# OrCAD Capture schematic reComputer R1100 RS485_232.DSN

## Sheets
1 01 RS485: size A3; rev: v1.0
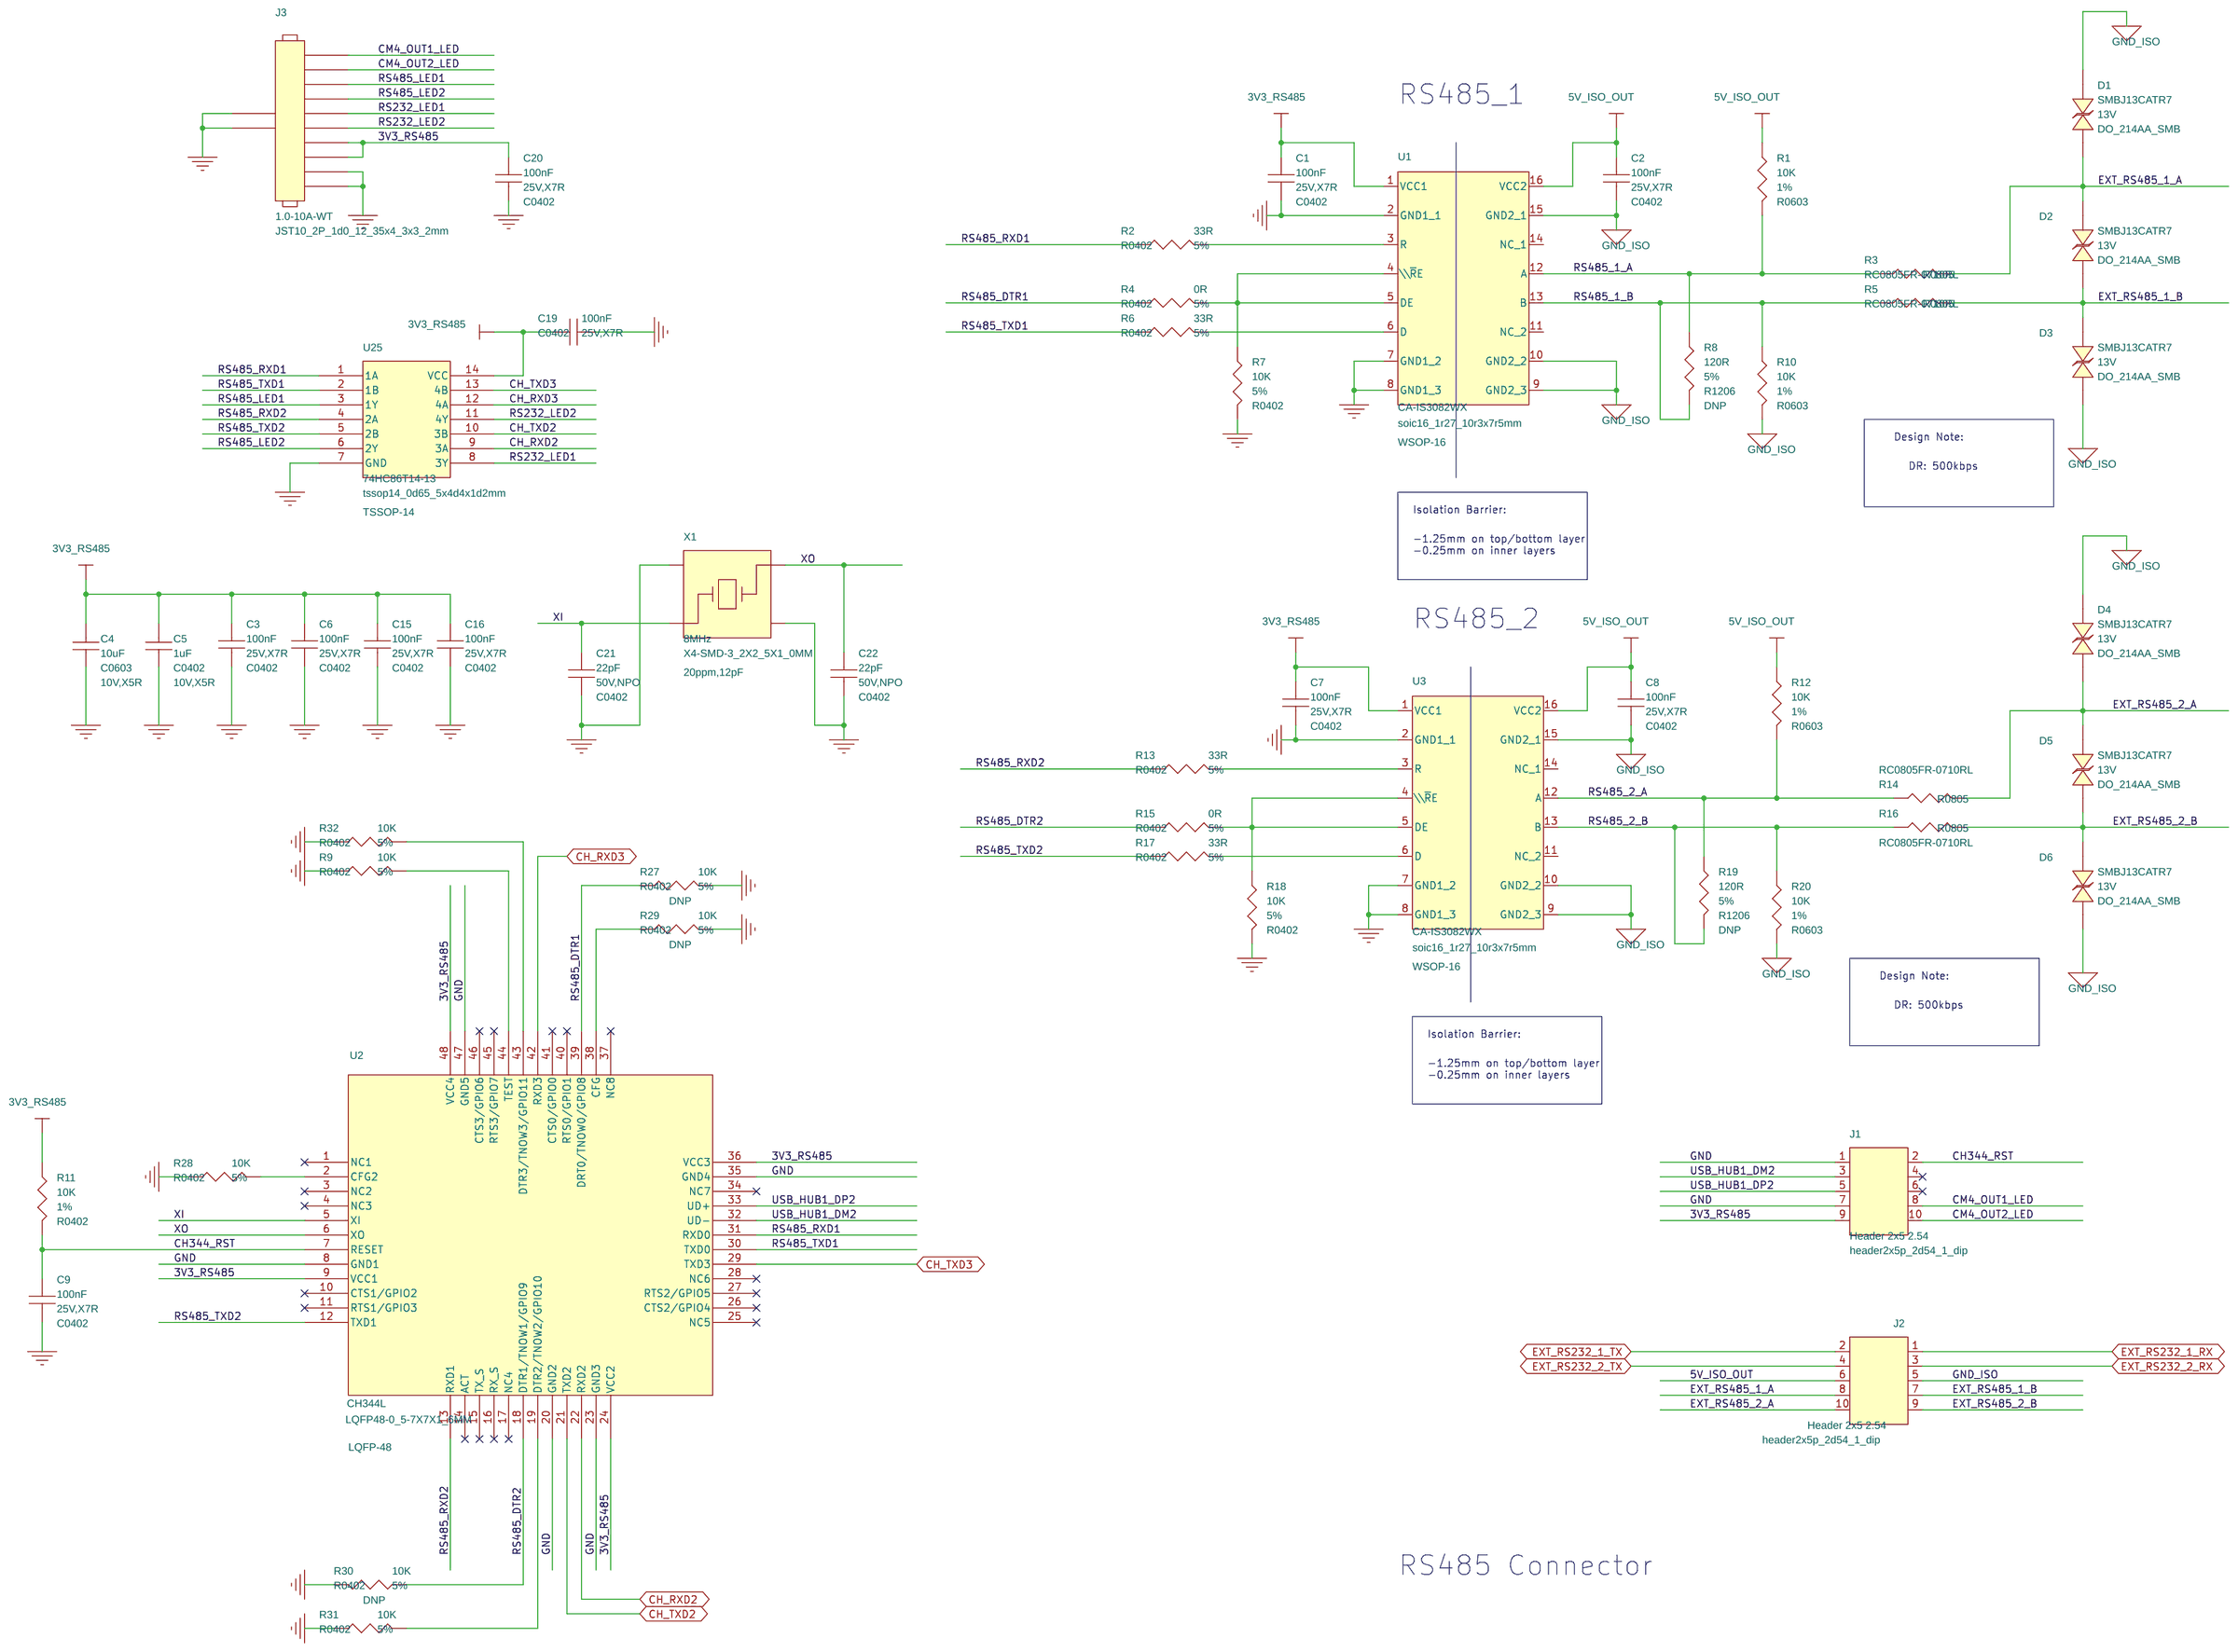
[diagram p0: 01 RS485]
2 02 RS232: size A3
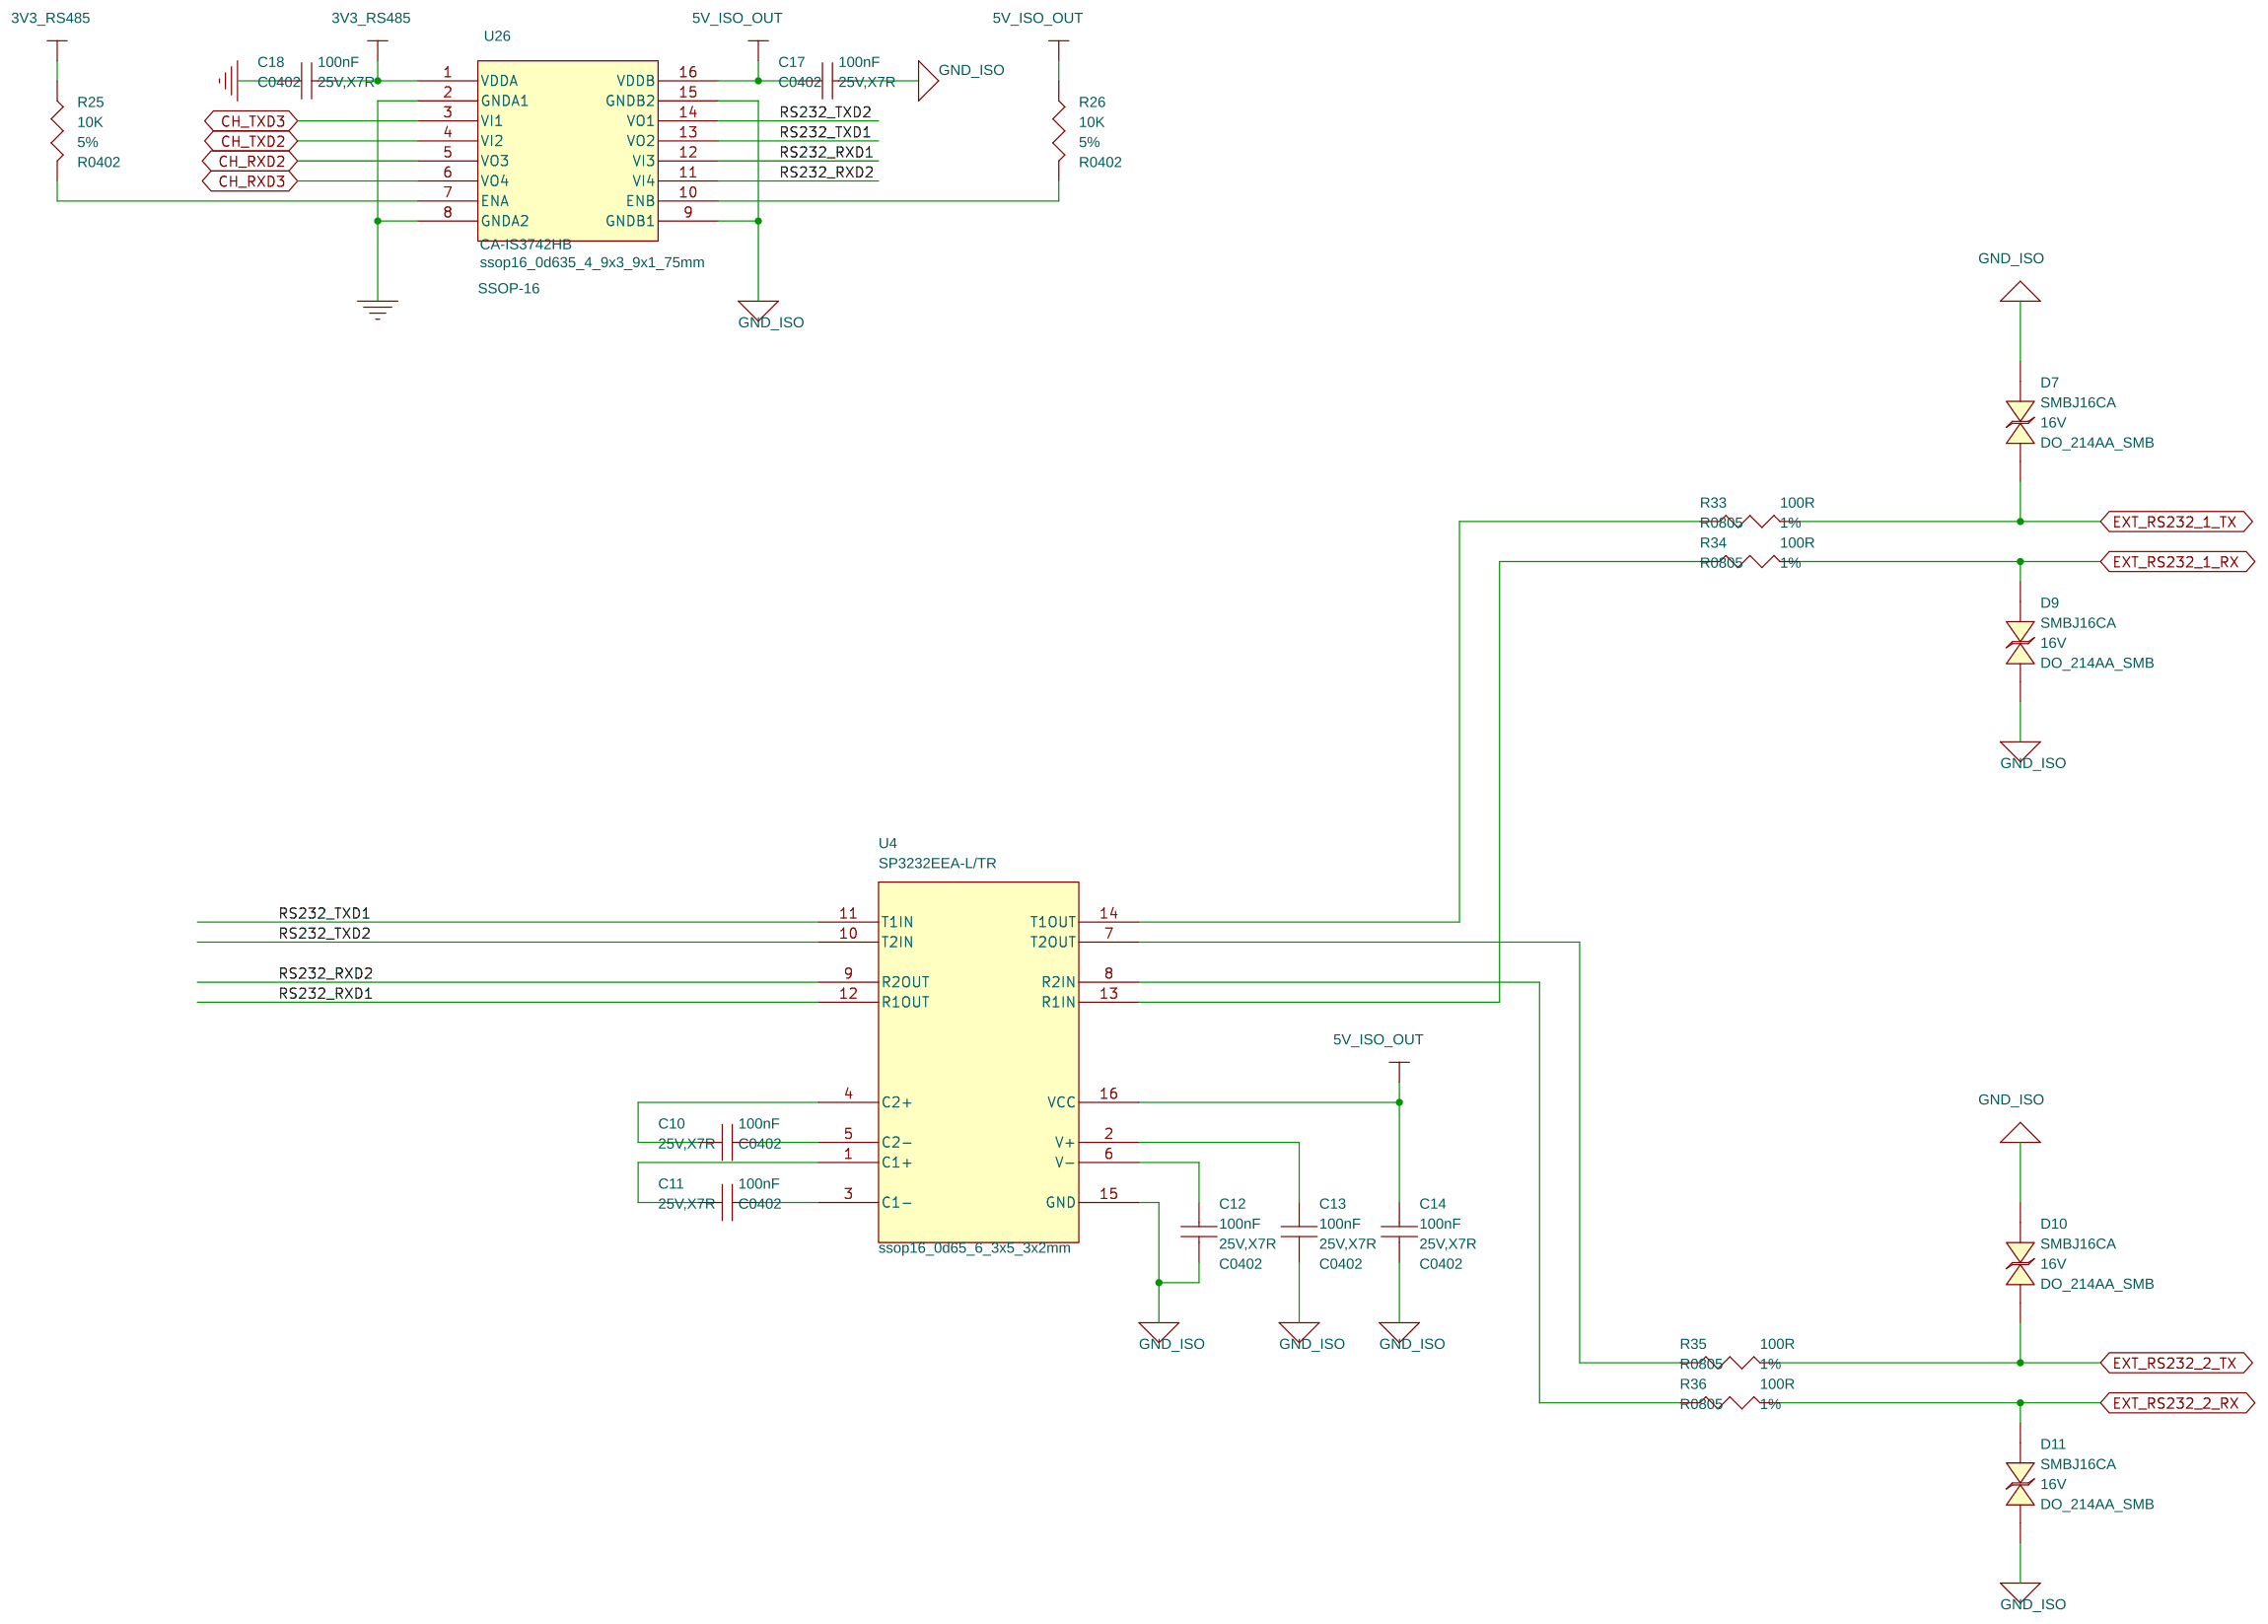
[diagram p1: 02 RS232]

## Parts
sheet 01 RS485
C1  100nF  [C0402]
C2  100nF  [C0402]
C3  100nF  [C0402]
C4  10uF  [C0603]
C5  1uF  [C0402]
C6  100nF  [C0402]
C7  100nF  [C0402]
C8  100nF  [C0402]
C9  100nF  [C0402]
C15  100nF  [C0402]
C16  100nF  [C0402]
C19  100nF  [C0402]
C20  100nF  [C0402]
C21  22pF  [C0402]
C22  22pF  [C0402]
D1  SMBJ13CATR7  [DO_214AA_SMB]
D2  SMBJ13CATR7  [DO_214AA_SMB]
D3  SMBJ13CATR7  [DO_214AA_SMB]
D4  SMBJ13CATR7  [DO_214AA_SMB]
D5  SMBJ13CATR7  [DO_214AA_SMB]
D6  SMBJ13CATR7  [DO_214AA_SMB]
J1  Header 2x5 2.54  [header2x5p_2d54_1_dip]
J2  Header 2x5 2.54  [header2x5p_2d54_1_dip]
J3  1.0-10A-WT  [JST10_2P_1d0_12_35x4_3x3_2mm]
R1  10K  [R0603]
R2  33R  [R0402]
R3  RC0805FR-0710RL  [R0805]
R4  0R  [R0402]
R5  RC0805FR-0710RL  [R0805]
R6  33R  [R0402]
R7  10K  [R0402]
R8  120R  [R1206]
R9  10K  [R0402]
R10  10K  [R0603]
R11  10K  [R0402]
R12  10K  [R0603]
R13  33R  [R0402]
R14  RC0805FR-0710RL  [R0805]
R15  0R  [R0402]
R16  RC0805FR-0710RL  [R0805]
R17  33R  [R0402]
R18  10K  [R0402]
R19  120R  [R1206]
R20  10K  [R0603]
R27  10K  [R0402]
R28  10K  [R0402]
R29  10K  [R0402]
R30  10K  [R0402]
R31  10K  [R0402]
R32  10K  [R0402]
U1  CA-IS3082WX  [soic16_1r27_10r3x7r5mm]
U2  CH344L  [LQFP48-0_5-7X7X1_6MM]
U3  CA-IS3082WX  [soic16_1r27_10r3x7r5mm]
U25  74HC86T14-13  [tssop14_0d65_5x4d4x1d2mm]
X1  8MHz  [X4-SMD-3_2X2_5X1_0MM]
sheet 02 RS232
C10  100nF  [C0402]
C11  100nF  [C0402]
C12  100nF  [C0402]
C13  100nF  [C0402]
C14  100nF  [C0402]
C17  100nF  [C0402]
C18  100nF  [C0402]
D7  SMBJ16CA  [DO_214AA_SMB]
D9  SMBJ16CA  [DO_214AA_SMB]
D10  SMBJ16CA  [DO_214AA_SMB]
D11  SMBJ16CA  [DO_214AA_SMB]
R25  10K  [R0402]
R26  10K  [R0402]
R33  100R  [R0805]
R34  100R  [R0805]
R35  100R  [R0805]
R36  100R  [R0805]
U4  SP3232EEA-L/TR  [ssop16_0d65_6_3x5_3x2mm]
U26  CA-IS3742HB  [ssop16_0d635_4_9x3_9x1_75mm]

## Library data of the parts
C1-C3 C6-C20 = CC: SMD CAP Ceramic 100nF-25V-10%-X7R;0402; CLASS: DISCRETE; Company Part Status: BeagleBone Carrier Board; Dielectric Type: Ceramic; Manufacturer: YAGEO; Manufacturer PN: CC0402KRX7R8BB104; Manufacturer Part Number: CC0402KRX7R8BB104; PN: 302010024; Package Size: 0402; Part Type: Ceramic; Rating: 25V,X7R; SIGNAL_MODEL: DEFAULT_CAPACITOR_100000pF_1_2; Status: BeagleBone Carrier Board; Temperature: -55°C to 125°C; Temperature Coefficient: X7R; Tolerance: 10%
C4 = CC: SMD CAP Ceramic 10uF-10V-10%-X5R;0603; CLASS: DISCRETE; Dielectric Type: Ceramic; Manufacturer: YAGEO; Manufacturer PN: CC0603MRX5R6BB226; Manufacturer Part Number: CC0603KRX5R6BB106; PN: 302010103; Package Size: 0603; Part Type: Ceramic; Rating: 10V,X5R; Status: BeagleBone Carrier Board; Temperature: -55°C to 85°C; Temperature Coefficient: X5R; Tolerance: 20%
C5 = CC: SMD CAP Ceramic 1uF-10V-10%-X5R;0402; CLASS: DISCRETE; Company Part Status: BeagleBone Carrier Board; Dielectric Type: Ceramic; Manufacturer: YAGEO; Manufacturer PN: CC0402KRX7R8BB104; Manufacturer Part Number: CC0402KRX5R6BB105; PN: 302010040; Package Size: 0402; Part Type: Ceramic; Rating: 10V,X5R; SIGNAL_MODEL: DEFAULT_CAPACITOR_100000pF_1_2; Status: BeagleBone Carrier Board; Temperature: -55°C to 85°C; Temperature Coefficient: X7R; Tolerance: 10%
C21 C22 = CC: SMD CAP Ceramic 22pF-50V-5%-NPO;0402; Manufacturer: YAGEO; Manufacturer Part Number: CC0402JRNPO9BN220; PN: 302010018; Package Size: 0402; Rating: 50V,NPO; Status: BeagleBone Carrier Board; Temperature: -55°C to 125°C
D1-D6 = DIODE_TVS_BI-DIR: SMD Diode TVS 13V-600W;DO-214AA; Manufacturer: BrightKing; PN: 304050965; Package Size: SMB; Part Type: TVS; Rating: 13V; Status: Sensecap one; Temperature: -55°C to 150°C
J1 J2 = Header_2X5: DIP Black Male Header;2*5P-2.54-2.54-11.6/3.0; Manufacturer: 思拓展; Manufacturer Part Number: PF-2075; PN: 320020122; Status: BBG
J3 = JST_10+2P: SMD Male 1.0mm; 10P+2P-1.00mm; Manufacturer: 思拓展; PN: 320112081; Package Size: 1.0-10P; Status: reComputer R1002; Temperature: -25°C to 70°C
R1 R10 R12 R20 = R: SMD RES 10K-1%-1/10W;0603; Manufacturer: YAGEO; Manufacturer Part Number: RC0603FR-0710KL; PN: 301010299; Package Size: 0603; Part Type: RES; Rating: 1%; SIGNAL_MODEL: DEFAULT_RESISTOR_10000OHM_1_2; Status: Sensecap Gateway V1; Temperature: -55°C to 155°C
R2 R6 R13 R17 = R: SMD RES 33R-5%-1/16W;0402; Manufacturer: YAGEO; Manufacturer Part Number: RC0402JR-0733RL; PN: 301010034; Package Size: 0402; Rating: 5%; Status: BeagleBone Carrier Board; Temperature: -55°C to 155°C
R3 R5 R14 R16 = R: SMD RES;10R-1/8W-1%-0805; PN: 301010583; Package Size: 0805; Status: reComputer R1002; Temperature: -55°C to 155°C
R4 R15 = R: SMD RES 0R-5%-1/16W;0402; Manufacturer: YAGEO; Manufacturer Part Number: RC0402JR-070RL; PN: 301010000; Package Size: 0402; Rating: 5%; Status: BeagleBone Carrier Board; Temperature: -55°C to 155°C
R7 R9 R18 R25 R26 R28 R31 R32 = R: SMD RES 10K-5%-1/16W;0402; Manufacturer: YAGEO; Manufacturer Part Number: RC0402JR-0710KL; PN: 301010004; Package Size: 0402; Rating: 5%; Status: BeagleBone Carrier Board; Temperature: -55°C to 155°C
R8 R19 = R: SMD RES 120R-5%-1/4W;1206; ASSY: DNP; Manufacturer: YAGEO; Manufacturer Part Number: RC1206JR-07120RL; PN: 301011878; Package Size: 1206; Part Type: RES; Rating: 5%; Status: BeagleBone Carrier Board; Temperature: -55°C to 155°C
R11 = R: SMD RES 10K-1%-1/16W;0402; Manufacturer: YAGEO; Manufacturer Part Number: RC0402FR-0710KL; PN: 301010047; Package Size: 0402; Part Type: RES; Rating: 1%; Status: BeagleBone Carrier Board; Temperature: -55°C to 155°C
R27 R29 R30 = R: SMD RES 10K-5%-1/16W;0402; ASSY: DNP; Manufacturer: YAGEO; Manufacturer Part Number: RC0402JR-0710KL; PN: 301010004; Package Size: 0402; Rating: 5%; Status: BeagleBone Carrier Board; Temperature: -55°C to 155°C
U1 U3 = ISO3082DW: SMD IC Interface RS485;WSOP-16; Manufacturer: Chipanalog; PN: TMP-750; Package Size: WSOP-16; Status: reComputer R1100; Temperature: -40°C to 125°C
U2 = CH344L: SMD IC Interface;USB to 4-Way-TTL;LQFP48-7*7; Manufacturer: WCH; PN: TMP-718; Package Size: LQFP-48; Status: reComputer R1100; Temperature: -40°C to 85°C
U25 = SN74AHC86: SMD IC XOR Logic 74HC86T14-13,TSSOP-14; Manufacturer: Diodes; PN: 310051510; Package Size: TSSOP-14; Status: reComputer CM4 R101; Temperature: -40°C to 150°C
X1 = XTAL_4P: SMD Crystal 16MHz-9pF-10ppm-60R;4P-SMD-3.2X2.5; Manufacturer: EPSON; Manufacturer Part Number: TSX-3225 16.0000MF18X-AC3; PN: 306010078; Package Size: 3.2x2.5mm; Rating: 20ppm,12pF; Status: ST; Temperature: -40°C to 85°C
D7 D9-D11 = DIODE_TVS_BI-DIR: SMD Diode TVS 16VWM 26V;SMB; Manufacturer: Littelfuse; PN: 304050009; Package Size: SMB; Rating: 16V; Status: BeagleBone Carrier Board
R33-R36 = R: SMD RES 100R-1%-1/8W;0805; Manufacturer: YAGEO; Manufacturer Part Number: RC0805FR-07100RL; PN: 301010371; Package Size: 0805; Rating: 1%; Status: Combox Pro; Temperature: -55°C to 155°C
U4 = SP3232EEA: SMD IC Interface 2-Way RS-232 Transceivers;SSOP-16; Manufacturer: Sipex; PN: 310071430; Part Type: Interface; Status: reTerminal Plus; Temperature: -40°C to 85°C
U26 = CA-IS3742LB: SMD Digital Isolator-4CH;SSOP-16; Manufacturer: Chipanalog; PN: TMP-719; Package Size: SSOP-16; Status: reComputer R1100; Temperature: -40°C to 125°C

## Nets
3V3_RS485: C1.1 C3.1 C4.2 C5.2 C6.1 C7.1 C15.1 C16.1 C18.2 C19.1 C20.1 J1.9 J3.7 J3.8 R11.1 R25.1 U1.1(VCC1) U2.9(VCC1) U2.24(VCC2) U2.36(VCC3) U2.48(VCC4) U3.1(VCC1) U25.14(VCC) U26.1(VDDA)
5V_ISO_OUT: C2.1 C8.1 C14.1 C17.1 J2.6 R1.1 R12.1 R26.1 U1.16(VCC2) U3.16(VCC2) U4.16(VCC) U26.16(VDDB)
GND: C1.2 C3.2 C4.1 C5.1 C6.2 C7.2 C9.2 C15.2 C16.2 C18.1 C19.2 C20.2 C21.2 C22.2 J1.1 J1.7 J3.9 J3.10 J3.S1 J3.S2 R7.2 R9.1 R18.2 R27.2 R28.1 R29.2 R30.2 R31.1 R32.1 U1.2(GND1_1) U1.7(GND1_2) U1.8(GND1_3) U2.8(GND1) U2.20(GND2) U2.23(GND3) U2.35(GND4) U2.47(GND5) U3.2(GND1_1) U3.7(GND1_2) U3.8(GND1_3) U25.7(GND) U26.2(GNDA1) U26.8(GNDA2) X1.2 X1.4
GND_ISO: C2.2 C8.2 C12.2 C13.2 C14.2 C17.2 D1.2 D3.1 D4.2 D6.1 D7.2 D9.1 D10.2 D11.1 J2.5 R10.2 R20.2 U1.9(GND2_3) U1.10(GND2_2) U1.15(GND2_1) U3.9(GND2_3) U3.10(GND2_2) U3.15(GND2_1) U4.15(GND) U26.9(GNDB1) U26.15(GNDB2)
CH344_RST: C9.1 J1.2 R11.2 U2.7(RESET)
CH_RXD2: U2.22(RXD2) U25.9(3A) U26.5(VO3)
CH_RXD3: U2.42(RXD3) U25.12(4A) U26.6(VO4)
CH_TXD2: U2.21(TXD2) U25.10(3B) U26.4(VI2)
CH_TXD3: U2.29(TXD3) U25.13(4B) U26.3(VI1)
CM4_OUT1_LED: J1.8 J3.1
CM4_OUT2_LED: J1.10 J3.2
EXT_RS232_1_RX: D9.2 J2.1 R34.2
EXT_RS232_1_TX: D7.1 J2.2 R33.2
EXT_RS232_2_RX: D11.2 J2.3 R36.2
EXT_RS232_2_TX: D10.1 J2.4 R35.2
EXT_RS485_1_A: D1.1 D2.2 J2.8 R3.2
EXT_RS485_1_B: D2.1 D3.2 J2.7 R5.2
EXT_RS485_2_A: D4.1 D5.2 J2.10 R14.2
EXT_RS485_2_B: D5.1 D6.2 J2.9 R16.2
RS232_LED1: J3.5 U25.8(3Y)
RS232_LED2: J3.6 U25.11(4Y)
RS232_RXD1: U4.12(R1OUT) U26.12(VI3)
RS232_RXD2: U4.9(R2OUT) U26.11(VI4)
RS232_TXD1: U4.11(T1IN) U26.13(VO2)
RS232_TXD2: U4.10(T2IN) U26.14(VO1)
RS485_1_A: R1.2 R3.1 R8.1 U1.12(A)
RS485_1_B: R5.1 R8.2 R10.1 U1.13(B)
RS485_2_A: R12.2 R14.1 R19.1 U3.12(A)
RS485_2_B: R16.1 R19.2 R20.1 U3.13(B)
RS485_DTR1: R4.1 R27.1 U2.39(DRT0/TNOW0/GPIO8)
RS485_DTR2: R15.1 R30.1 U2.18(DTR1/TNOW1/GPIO9)
RS485_LED1: J3.3 U25.3(1Y)
RS485_LED2: J3.4 U25.6(2Y)
RS485_RXD1: R2.1 U2.31(RXD0) U25.1(1A)
RS485_RXD2: R13.1 U2.13(RXD1) U25.4(2A)
RS485_TXD1: R6.1 U2.30(TXD0) U25.2(1B)
RS485_TXD2: R17.1 U2.12(TXD1) U25.5(2B)
USB_HUB1_DM2: J1.3 U2.32(UD-)
USB_HUB1_DP2: J1.5 U2.33(UD+)
XI: C21.1 U2.5(XI) X1.1
XO: C22.1 U2.6(XO) X1.3
N02289: R2.2 U1.3(R)
N02317: R4.2 R7.1 U1.4(\\~{R}E) U1.5(DE)
N02517: R6.2 U1.6(D)
N03671: R13.2 U3.3(R)
N03703: R15.2 R18.1 U3.4(\\~{R}E) U3.5(DE)
N03887: R17.2 U3.6(D)
N14484: R33.1 U4.14(T1OUT)
N14512: R35.1 U4.7(T2OUT)
N14652: C10.1 U4.4(C2+)
N14700: C10.2 U4.5(C2-)
N14704: C13.1 U4.2(V+)
N14712: C11.1 U4.1(C1+)
N14720: C12.1 U4.6(V-)
N14756: C11.2 U4.3(C1-)
N15316: R31.2 U2.19(DTR2/TNOW2/GPIO10)
N19896: R9.2 U2.44(TEST)
N22670: R25.2 U26.7(ENA)
N23580: R26.2 U26.10(ENB)
N26778: R29.1 U2.38(CFG)
N27410: R28.2 U2.2(CFG2)
N30228: R32.2 U2.43(DTR3/TNOW3/GPIO11)
N33687: R34.1 U4.13(R1IN)
N34139: R36.1 U4.8(R2IN)

Not connected (* = marked no-connect by the designer): J1 4* 6*; U1 11(NC_2) 14(NC_1); U2 1(NC1)* 3(NC2)* 4(NC3)* 10(CTS1/GPIO2)* 11(RTS1/GPIO3)* 14(ACT)* 15(TX_S)* 16(RX_S)* 17(NC4)* 25(NC5)* 26(CTS2/GPIO4)* 27(RTS2/GPIO5)* 28(NC6)* 34(NC7)* 37(NC8)* 40(RTS0/GPIO1)* 41(CTS0/GPIO0)* 45(RTS3/GPIO7)* 46(CTS3/GPIO6)*; U3 11(NC_2) 14(NC_1)

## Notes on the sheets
sheet 1
- RS485_1
- Design Note:
- DR: 500kbps
- Isolation Barrier:
- -1.25mm on top/bottom layer
  -0.25mm on inner layers
- RS485_2
- Design Note:
- DR: 500kbps
- Isolation Barrier:
- -1.25mm on top/bottom layer
  -0.25mm on inner layers
- RS485 Connector
